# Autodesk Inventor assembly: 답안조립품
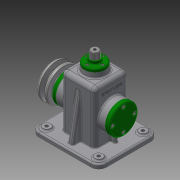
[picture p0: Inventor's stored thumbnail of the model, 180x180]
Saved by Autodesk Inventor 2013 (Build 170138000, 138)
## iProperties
Created: 2016-01
Part Number: 답안조립품
Document SubType Name: Assembly
Designer: User
Author: User
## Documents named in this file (19)
- C:\Users\User\Desktop\460126V1001\답안조립품.iam
- C:\Users\User\Desktop\460126V1001\본체.ipt
- C:\Users\User\Desktop\460126V1001\뒤커버.ipt
- C:\Users\User\Desktop\460126V1001\볼트 M4 x 10.ipt
- C:\Users\User\Desktop\460126V1001\상부부시.ipt
- C:\Users\User\Desktop\460126V1001\볼트 M3 x 8.ipt
- C:\Users\User\Desktop\460126V1001\오일실 15 25 7.ipt
- C:\Users\User\Desktop\460126V1001\앞커버.ipt
- C:\Users\User\Desktop\460126V1001\베어링 15 x 35 x 11.ipt
- C:\Users\User\Desktop\460126V1001\편심축.ipt
- C:\Users\User\Desktop\460126V1001\멈춤링 15 x 1.ipt
- C:\Users\User\Desktop\460126V1001\키 5 x 5 x 14.ipt
- C:\Users\User\Desktop\460126V1001\V-벨트풀리.ipt
- C:\Users\User\Desktop\460126V1001\와셔.ipt
- C:\Users\User\Desktop\460126V1001\볼트 M6 x 12.ipt
- C:\Users\User\Desktop\460126V1001\링크.ipt
- C:\Users\User\Desktop\460126V1001\고정핀.ipt
- C:\Users\User\Desktop\460126V1001\멈춤링 6 x 5.ipt
- C:\Users\User\Desktop\460126V1001\슬라이드바.ipt
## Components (15 placed, 5 different names)
1. V-벨트풀리:1 — 각도:1
2. ISO 4018 M6 x 12:1 — 각도:2
3. 고정핀:1
4. ISO 4762 M4 x 10:1
5. ISO 4762 M4 x 10:6
6. ISO 4762 M4 x 10:7
7. ISO 4762 M4 x 10:8
8. ISO 4762 M3 x 8:1
9. ISO 4762 M3 x 8:2
10. ISO 4762 M3 x 8:3
11. ISO 4762 M3 x 8:4
12. ISO 4762 M4 x 10:2
13. ISO 4762 M4 x 10:9
14. ISO 4762 M4 x 10:10
15. ISO 4762 M4 x 10:11
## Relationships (2: Angle 2)
- 각도:1 [Angle]: V-벨트풀리:1
- 각도:2 [Angle]: ISO 4018 M6 x 12:1
